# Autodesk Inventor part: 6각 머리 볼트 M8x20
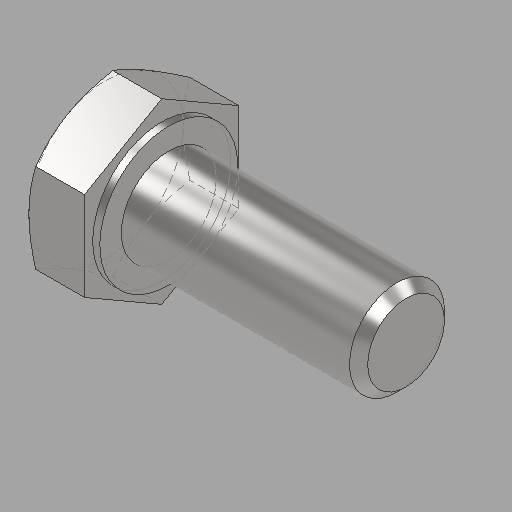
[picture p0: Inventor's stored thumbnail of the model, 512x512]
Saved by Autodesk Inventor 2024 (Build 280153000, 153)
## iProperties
Created: 2025-11
Part Number: 6각 머리 볼트 M8x20
Material: 강철, 연강
Description: 6각 머리 볼트 및 6각 머리 나사
Document SubType Name: Modeling
Designer: Edu09
Density: 7.85 g/cm^3
Appearance: 기본값
Author: jhkim
Sending System: Autodesk Inventor 2026
Preprocessor: ST-DEVELOPER v20.1
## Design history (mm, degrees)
feature "Solid1"
node "솔리드1"
